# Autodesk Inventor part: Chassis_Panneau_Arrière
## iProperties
Created: 2008-12
Part Number: Chassis_Panneau_Arrière
Document SubType Name: Sheet Metal
Designer: claivier
Author: claivier
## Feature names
1. Extrusion1
2. Extrusion2
3. Perçage1 [Hole]
4. Perçage2 [Hole]
5. Perçage3 [Hole]
6. Perçage4 [Hole]
7. Miroir1 [Mirror]
8. Extrusion3
9. Extrusion4
10. Perçage5 [Hole]
11. Extrusion5
12. Plaque1
13. Pli1
14. Couper1
15. Couper3
16. Couper4
